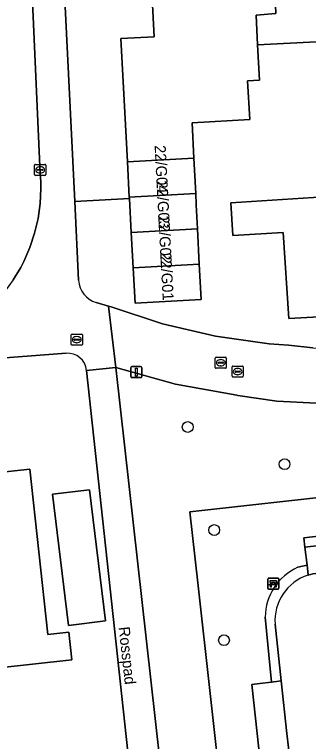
# Model space of a CAD drawing. Extents: x 161248 to 161848, y 384871 to 385383.
# Drawn here: x 161394.3 to 161420.9, y 385265.7 to 385331.7 of the extents above; entities that cross this region are included whole.
import ezdxf

# ---------------------------------------------------------------- set-up
doc = ezdxf.new("R2010")
doc.units = 0
for name, color, linetype in [('IMGEO_Bank', 7, 'Continuous'), ('IMGEO_Boom', 7, 'Continuous'), ('IMGEO_Brandkraan', 7, 'Continuous'), ('IMGEO_Erf', 7, 'Continuous'), ('IMGEO_Groenvoorziening', 7, 'Continuous'), ('IMGEO_Hek', 7, 'Continuous'), ('IMGEO_Kolk', 7, 'Continuous'), ('IMGEO_Lichtmast', 7, 'Continuous'), ('IMGEO_Openbare_ruimte_label', 7, 'Continuous'), ('IMGEO_Pand', 7, 'Continuous'), ('IMGEO_Pand_nummerreeks', 7, 'Continuous'), ('IMGEO_Rijbaan_lokaal_open', 7, 'Continuous'), ('IMGEO_Rioolput', 7, 'Continuous'), ('IMGEO_Voetpad_gesloten', 7, 'Continuous'), ('IMGEO_Voetpad_open', 7, 'Continuous')]:
    doc.layers.add(name, color=color, linetype=linetype)

msp = doc.modelspace()

# ---------------------------------------------------------------- linework, layer by layer
at = {"layer": 'IMGEO_Bank'}
for p, q in [((161417.227, 385279.617), (161417.227, 385280.458)), ((161417.227, 385280.458), (161417.227, 385279.617)), ((161417.302, 385280.542), (161418.143, 385280.542)), ((161418.143, 385280.542), (161417.302, 385280.542)), ((161418.227, 385280.467), (161418.227, 385279.626)), ((161418.227, 385279.626), (161418.227, 385280.467)), ((161417.924, 385279.94), (161417.531, 385279.94)), ((161417.536, 385280.048), (161417.536, 385280.154)), ((161417.58, 385280.154), (161417.58, 385280.048)), ((161417.868, 385280.16), (161417.586, 385280.16)), ((161417.586, 385280.042), (161417.868, 385280.042)), ((161417.874, 385280.048), (161417.874, 385280.154)), ((161417.918, 385280.154), (161417.918, 385280.048)), ((161418.152, 385279.542), (161417.311, 385279.542)), ((161417.311, 385279.542), (161418.152, 385279.542))]:
    msp.add_line(p, q, dxfattribs=at)
for points in [[(161417.474, 385279.94), (161417.332, 385279.94), (161417.444, 385280.042), (161417.53, 385280.042)], [(161417.53, 385280.16), (161417.444, 385280.16), (161417.444, 385280.321), (161418.007, 385280.321), (161418.007, 385280.16), (161417.924, 385280.16)], [(161417.524, 385279.933), (161417.524, 385279.726), (161417.481, 385279.726), (161417.481, 385279.933)], [(161417.924, 385280.042), (161418.007, 385280.042), (161418.119, 385279.94), (161417.98, 385279.94)], [(161417.974, 385279.933), (161417.974, 385279.726), (161417.93, 385279.726), (161417.93, 385279.933)]]:
    msp.add_lwpolyline(points, dxfattribs=at)
for centre, radius, start, end in [((161417.305, 385280.464), 0.0779, 92.4484, 184.28452), ((161417.305, 385280.464), 0.0779, 92.4484, 184.28452), ((161418.149, 385280.464), 0.0779, 2.4484, 94.28452), ((161418.149, 385280.464), 0.0779, 2.4484, 94.28452), ((161417.474, 385279.933), 0.00671, 2.89567, 87.10433), ((161417.531, 385279.933), 0.00671, 92.89567, 177.10433), ((161417.529, 385280.153), 0.00671, 2.89567, 87.10433), ((161417.529, 385280.049), 0.00671, 272.89567, 357.10433), ((161417.586, 385280.153), 0.00671, 92.89567, 177.10433), ((161417.586, 385280.049), 0.00671, 182.89567, 267.10433), ((161417.868, 385280.153), 0.00671, 2.89567, 87.10433), ((161417.868, 385280.049), 0.00671, 272.89567, 357.10433), ((161417.925, 385280.153), 0.00671, 92.89567, 177.10433), ((161417.925, 385280.049), 0.00671, 182.89567, 267.10433), ((161417.923, 385279.933), 0.00671, 2.89567, 87.10433), ((161417.98, 385279.933), 0.00671, 92.89567, 177.10433), ((161417.305, 385279.62), 0.0779, 182.4484, 274.28452), ((161417.305, 385279.62), 0.0779, 182.4484, 274.28452), ((161418.149, 385279.62), 0.0779, 272.4484, 4.28452), ((161418.149, 385279.62), 0.0779, 272.4484, 4.28452)]:
    msp.add_arc(centre, radius, start, end, dxfattribs=at)
at = {"layer": 'IMGEO_Boom'}
for centre in [(161409.973, 385294.249), (161418.745, 385290.874), (161412.374, 385284.907), (161413.26, 385274.915)]:
    msp.add_circle(centre, 0.489, dxfattribs=at)
at = {"layer": 'IMGEO_Brandkraan'}
for p, q in [((161399.432, 385301.745), (161399.432, 385302.597)), ((161399.507, 385302.671), (161400.359, 385302.671)), ((161399.691, 385302.165), (161399.691, 385302.177)), ((161399.734, 385302.214), (161400.132, 385302.214)), ((161399.92, 385302.451), (161399.945, 385302.451)), ((161400.175, 385302.177), (161400.175, 385302.165)), ((161400.433, 385302.597), (161400.433, 385301.745)), ((161400.359, 385301.671), (161399.507, 385301.671)), ((161400.129, 385302.128), (161399.731, 385302.128)), ((161399.943, 385301.891), (161399.918, 385301.891))]:
    msp.add_line(p, q, dxfattribs=at)
for points in [[(161399.432, 385301.745), (161399.432, 385302.597)], [(161399.507, 385302.671), (161400.359, 385302.671)], [(161400.433, 385302.597), (161400.433, 385301.745)], [(161400.359, 385301.671), (161399.507, 385301.671)]]:
    msp.add_lwpolyline(points, dxfattribs=at)
for centre, radius, start, end in [((161399.509, 385302.595), 0.0765, 91.55205, 178.44795), ((161399.509, 385302.595), 0.0765, 91.55205, 178.44795), ((161399.731, 385302.174), 0.0403, 85.87752, 175.75265), ((161399.728, 385302.164), 0.0366, 178.93798, 274.71019), ((161400.132, 385302.171), 0.043, 264.86636, 352.45326), ((161400.136, 385302.176), 0.0386, 1.73085, 96.63898), ((161400.357, 385302.595), 0.0765, 1.55205, 88.44795), ((161400.357, 385302.595), 0.0765, 1.55205, 88.44795), ((161399.509, 385301.747), 0.0765, 181.55205, 268.44795), ((161399.509, 385301.747), 0.0765, 181.55205, 268.44795), ((161400.357, 385301.747), 0.0765, 271.55205, 358.44795), ((161400.357, 385301.747), 0.0765, 271.55205, 358.44795)]:
    msp.add_arc(centre, radius, start, end, dxfattribs=at)
for centre, major_axis, ratio, start_param, end_param in [((161399.919, 385302.171), (-0.387, 0.002), 0.722429, 4.712389, 7.853982), ((161399.944, 385302.171), (-0.39, 0.002), 0.717154, 1.570796, 4.712389)]:
    msp.add_ellipse(centre, major_axis=major_axis, ratio=ratio, start_param=start_param, end_param=end_param, dxfattribs=at)
at = {"layer": 'IMGEO_Erf'}
for points in [[(161398.601, 385337.878), (161399.745, 385314.686), (161404.692, 385314.964), (161404.684, 385315.106), (161404.511, 385318.31), (161403.906, 385329.475), (161406.945, 385329.635), (161406.547, 385337.179)], [(161423.98, 385329.306), (161416.302, 385328.911), (161416.466, 385325.699), (161415.383, 385325.643), (161415.587, 385322.128), (161410.366, 385321.824), (161410.531, 385318.619), (161410.695, 385315.414), (161410.748, 385314.385), (161410.86, 385312.21), (161411.024, 385309.005), (161411.189, 385305.8), (161405.205, 385305.492), (161405.031, 385308.697), (161404.858, 385311.901), (161404.692, 385314.964), (161399.745, 385314.686), (161400.097, 385307.562)], [(161401.692, 385305.534), (161402.809, 385305.204), (161403.042, 385305.135), (161407.703, 385303.597), (161412.483, 385302.481), (161417.343, 385301.797), (161419.104, 385301.658), (161421.316, 385301.428), (161423.54, 385301.396), (161425.328, 385301.515), (161433.495, 385302.03), (161432.821, 385315.408)], [(161398.96, 385300.934), (161391.455, 385300.374)], [(161391.744, 385183.5), (161396.212, 385183.986), (161401.98, 385184.625), (161402.139, 385184.643), (161406.592, 385185.134), (161412.682, 385185.849), (161413.106, 385185.96), (161411.781, 385198.48), (161406.165, 385250), (161400.82, 385299.379)], [(161379.033, 385288.611), (161395.673, 385290.437), (161397.318, 385275.442), (161399.197, 385275.648), (161399.473, 385273.133), (161382.449, 385271.265)]]:
    msp.add_lwpolyline(points, dxfattribs=at)
for points in [[(161426.057, 385315.361), (161426.125, 385314.29), (161430.906, 385314.594), (161431.245, 385309.259), (161431.911, 385309.3), (161432.236, 385304.186), (161421.893, 385303.639), (161421.861, 385304.249), (161419.12, 385304.103), (161418.623, 385311.901), (161414.063, 385311.61), (161413.873, 385314.584)], [(161399.175, 385276.249), (161397.723, 385288.146), (161401.081, 385288.556), (161402.534, 385276.659)]]:
    msp.add_lwpolyline(points, close=True, dxfattribs=at)
for centre, radius, start, end in [((161402.323, 385307.672), 2.229, 182.81721, 253.55213), ((161399.091, 385299.2), 1.739, 5.89689, 94.31041)]:
    msp.add_arc(centre, radius, start, end, dxfattribs=at)
at = {"layer": 'IMGEO_Groenvoorziening'}
for points in [[(161414.256, 385250), (161410.885, 385280.109), (161410.162, 385286.563), (161475.044, 385293.779), (161521.676, 385299.004), (161534.85, 385300.481), (161543.938, 385301.499), (161569.562, 385304.383), (161586.988, 385306.345), (161622.8, 385310.376), (161633.809, 385311.615), (161634.458, 385305.787), (161634.818, 385302.549), (161643.668, 385222.865)], [(161543.364, 385306.723), (161500, 385302.086), (161474.798, 385299.391), (161474.909, 385297.26), (161471.889, 385297.103), (161471.879, 385297.287), (161464.205, 385296.931), (161464.206, 385296.907), (161462.414, 385296.814), (161462.412, 385296.848), (161450.838, 385296.312), (161450.732, 385298.359), (161445.594, 385298.092), (161445.597, 385297.541), (161424.736, 385296.492), (161421.626, 385296.405), (161418.051, 385296.604), (161414.509, 385297.121), (161414.415, 385297.134), (161408.88, 385298.145), (161403.458, 385299.646), (161409.014, 385250)], [(161419.938, 385281.527), (161420.776, 385281.731), (161420.588, 385283.368), (161420.493, 385284.196), (161444.677, 385286.979), (161444.772, 385286.151), (161445.027, 385283.936), (161445.061, 385283.659), (161449.189, 385284.134), (161448.902, 385286.626), (161448.807, 385287.454), (161521.926, 385295.866), (161521.676, 385299.004), (161475.044, 385293.779), (161410.162, 385286.563), (161410.885, 385280.109), (161414.256, 385250)], [(161420.878, 385280.815), (161420.843, 385281.153), (161420.776, 385281.731), (161419.938, 385281.527)], [(161416.555, 385263.685), (161415.768, 385270.902), (161416.49, 385270.991), (161417.55, 385271.121), (161416.996, 385277.006)], [(161416.996, 385277.006), (161417.55, 385271.121), (161418.237, 385271.205), (161418.44, 385271.231), (161417.881, 385276.364)]]:
    msp.add_lwpolyline(points, dxfattribs=at)
for points in [[(161444.772, 385286.151), (161444.677, 385286.979), (161420.493, 385284.196), (161420.588, 385283.368)], [(161445.061, 385283.659), (161445.027, 385283.936), (161444.772, 385286.151), (161420.588, 385283.368), (161420.776, 385281.731), (161420.843, 385281.153), (161420.878, 385280.815), (161421.089, 385280.877), (161421.302, 385280.928)], [(161418.44, 385271.231), (161418.237, 385271.205), (161417.55, 385271.121), (161416.49, 385270.991), (161415.768, 385270.902), (161416.555, 385263.685), (161417.863, 385263.793), (161419.035, 385263.89), (161419.237, 385263.908), (161418.959, 385266.457)]]:
    msp.add_lwpolyline(points, close=True, dxfattribs=at)
for centre, radius, start, end in [((161421.995, 385276.97), 4.999, 114.29995, 179.59264), ((161421.995, 385276.97), 4.999, 114.29995, 179.59264), ((161422.208, 385276.685), 4.339, 107.8532, 184.23952)]:
    msp.add_arc(centre, radius, start, end, dxfattribs=at)
at = {"layer": 'IMGEO_Hek'}
for points in [[(161410.162, 385286.563), (161475.044, 385293.779)], [(161410.885, 385280.109), (161410.162, 385286.563)], [(161418.32, 385212.789), (161414.256, 385250), (161410.885, 385280.109)]]:
    msp.add_lwpolyline(points, dxfattribs=at)
at = {"layer": 'IMGEO_Kolk'}
for p, q in [((161396.116, 385317.142), (161396.116, 385317.994)), ((161396.191, 385318.068), (161397.043, 385318.068)), ((161397.117, 385317.994), (161397.117, 385317.142)), ((161396.375, 385317.562), (161396.375, 385317.574)), ((161396.813, 385317.525), (161396.415, 385317.525)), ((161396.418, 385317.611), (161396.816, 385317.611)), ((161396.604, 385317.848), (161396.629, 385317.848)), ((161396.859, 385317.574), (161396.859, 385317.562)), ((161397.043, 385317.068), (161396.191, 385317.068)), ((161396.627, 385317.288), (161396.602, 385317.288)), ((161412.466, 385299.651), (161412.466, 385300.503)), ((161412.541, 385300.577), (161413.393, 385300.577)), ((161412.954, 385300.357), (161412.979, 385300.357)), ((161413.467, 385300.503), (161413.467, 385299.651)), ((161413.393, 385299.577), (161412.541, 385299.577)), ((161412.725, 385300.071), (161412.725, 385300.083)), ((161413.163, 385300.034), (161412.765, 385300.034)), ((161412.768, 385300.12), (161413.166, 385300.12)), ((161412.977, 385299.797), (161412.952, 385299.797)), ((161413.209, 385300.083), (161413.209, 385300.071))]:
    msp.add_line(p, q, dxfattribs=at)
for points in [[(161396.116, 385317.142), (161396.116, 385317.994)], [(161396.191, 385318.068), (161397.043, 385318.068)], [(161397.117, 385317.994), (161397.117, 385317.142)], [(161397.043, 385317.068), (161396.191, 385317.068)], [(161412.466, 385299.651), (161412.466, 385300.503)], [(161412.541, 385300.577), (161413.393, 385300.577)], [(161413.467, 385300.503), (161413.467, 385299.651)], [(161413.393, 385299.577), (161412.541, 385299.577)]]:
    msp.add_lwpolyline(points, dxfattribs=at)
for centre, radius, start, end in [((161396.193, 385317.992), 0.0765, 91.55205, 178.44795), ((161396.193, 385317.992), 0.0765, 91.55205, 178.44795), ((161397.041, 385317.992), 0.0765, 1.55205, 88.44795), ((161397.041, 385317.992), 0.0765, 1.55205, 88.44795), ((161396.415, 385317.571), 0.0403, 85.87752, 175.75265), ((161396.412, 385317.561), 0.0366, 178.93798, 274.71019), ((161396.816, 385317.568), 0.043, 264.86636, 352.45326), ((161396.82, 385317.573), 0.0386, 1.73085, 96.63898), ((161396.193, 385317.144), 0.0765, 181.55205, 268.44795), ((161396.193, 385317.144), 0.0765, 181.55205, 268.44795), ((161397.041, 385317.144), 0.0765, 271.55205, 358.44795), ((161397.041, 385317.144), 0.0765, 271.55205, 358.44795), ((161412.543, 385300.501), 0.0765, 91.55205, 178.44795), ((161412.543, 385300.501), 0.0765, 91.55205, 178.44795), ((161413.391, 385300.501), 0.0765, 1.55205, 88.44795), ((161413.391, 385300.501), 0.0765, 1.55205, 88.44795), ((161412.543, 385299.653), 0.0765, 181.55205, 268.44795), ((161412.543, 385299.653), 0.0765, 181.55205, 268.44795), ((161412.765, 385300.08), 0.0403, 85.87752, 175.75265), ((161412.762, 385300.07), 0.0366, 178.93798, 274.71019), ((161413.166, 385300.077), 0.043, 264.86636, 352.45326), ((161413.17, 385300.082), 0.0386, 1.73085, 96.63898), ((161413.391, 385299.653), 0.0765, 271.55205, 358.44795), ((161413.391, 385299.653), 0.0765, 271.55205, 358.44795)]:
    msp.add_arc(centre, radius, start, end, dxfattribs=at)
for centre, major_axis, ratio, start_param, end_param in [((161396.603, 385317.568), (-0.387, 0.002), 0.722429, 4.712389, 7.853982), ((161396.628, 385317.568), (-0.39, 0.002), 0.717154, 1.570796, 4.712389), ((161412.953, 385300.077), (-0.387, 0.002), 0.722429, 4.712389, 7.853982), ((161412.978, 385300.077), (-0.39, 0.002), 0.717154, 1.570796, 4.712389)]:
    msp.add_ellipse(centre, major_axis=major_axis, ratio=ratio, start_param=start_param, end_param=end_param, dxfattribs=at)
at = {"layer": 'IMGEO_Lichtmast'}
for p, q in [((161404.819, 385298.824), (161404.819, 385299.624)), ((161404.819, 385299.624), (161404.819, 385298.824)), ((161404.919, 385299.724), (161405.709, 385299.724)), ((161405.709, 385299.724), (161404.919, 385299.724)), ((161405.809, 385299.624), (161405.809, 385298.824)), ((161405.809, 385298.824), (161405.809, 385299.624)), ((161405.709, 385298.724), (161404.919, 385298.724)), ((161404.919, 385298.724), (161405.709, 385298.724))]:
    msp.add_line(p, q, dxfattribs=at)
msp.add_lwpolyline([(161405.239, 385299.599), (161405.389, 385299.599), (161405.389, 385298.849), (161405.239, 385298.849), (161405.239, 385299.599)], dxfattribs=at)
for centre, start, end in [((161404.919, 385299.624), 90, 180), ((161404.919, 385299.624), 90, 180), ((161405.709, 385299.624), 0, 90), ((161405.709, 385299.624), 360, 90), ((161404.919, 385298.824), 180, 270), ((161404.919, 385298.824), 180, 270), ((161405.709, 385298.824), 270, 0), ((161405.709, 385298.824), 270, 0)]:
    msp.add_arc(centre, 0.1, start, end, dxfattribs=at)
at = {"layer": 'IMGEO_Pand'}
for points in [[(161427.998, 385338.318), (161419.808, 385337.885), (161419.889, 385336.345), (161417.772, 385336.233), (161417.951, 385331.733), (161416.162, 385331.603), (161416.302, 385328.911), (161423.98, 385329.306), (161424.53, 385318.636), (161425.276, 385318.674), (161428.76, 385318.853), (161429.025, 385318.867)], [(161413.405, 385336.002), (161413.324, 385337.537), (161406.547, 385337.179), (161406.945, 385329.635), (161403.906, 385329.475), (161404.511, 385318.31), (161410.531, 385318.619), (161410.366, 385321.824), (161415.587, 385322.128), (161415.383, 385325.643), (161416.466, 385325.699), (161416.302, 385328.911), (161416.162, 385331.603), (161417.951, 385331.733), (161417.772, 385336.233)], [(161404.684, 385315.106), (161410.695, 385315.414), (161410.531, 385318.619), (161404.511, 385318.31)], [(161404.692, 385314.964), (161404.858, 385311.901), (161410.86, 385312.21), (161410.748, 385314.385), (161410.695, 385315.414), (161404.684, 385315.106)], [(161414.063, 385311.61), (161418.623, 385311.901), (161419.12, 385304.103), (161421.861, 385304.249), (161421.893, 385303.639), (161432.236, 385304.186), (161431.911, 385309.3), (161431.245, 385309.259), (161430.906, 385314.594), (161426.125, 385314.29), (161426.057, 385315.361), (161413.873, 385314.584)], [(161405.031, 385308.697), (161411.024, 385309.005), (161410.86, 385312.21), (161404.858, 385311.901)], [(161405.205, 385305.492), (161411.189, 385305.8), (161411.024, 385309.005), (161405.031, 385308.697)], [(161399.175, 385276.249), (161402.534, 385276.659), (161401.081, 385288.556), (161397.723, 385288.146)]]:
    msp.add_lwpolyline(points, close=True, dxfattribs=at)
msp.add_lwpolyline([(161382.449, 385271.265), (161399.473, 385273.133), (161399.197, 385275.648), (161397.318, 385275.442), (161395.673, 385290.437), (161379.033, 385288.611)], dxfattribs=at)
at = {"layer": 'IMGEO_Rijbaan_lokaal_open'}
for points in [[(161394.178, 385307.586), (161394.868, 385308.726), (161395.144, 385309.256), (161395.685, 385310.515), (161396.112, 385311.817), (161396.42, 385313.152), (161396.609, 385314.509), (161396.675, 385315.878), (161396.664, 385316.508), (161396.614, 385317.218), (161395.736, 385336.901)], [(161421.316, 385301.428), (161419.104, 385301.658), (161417.343, 385301.797), (161412.483, 385302.481), (161407.703, 385303.597), (161403.042, 385305.135), (161402.809, 385305.204), (161403.458, 385299.646), (161408.88, 385298.145), (161414.415, 385297.134), (161414.509, 385297.121), (161418.051, 385296.604), (161421.626, 385296.405)]]:
    msp.add_lwpolyline(points, dxfattribs=at)
at = {"layer": 'IMGEO_Rioolput'}
for p, q in [((161413.997, 385298.848), (161413.997, 385299.7)), ((161414.072, 385299.774), (161414.924, 385299.774)), ((161414.485, 385299.554), (161414.51, 385299.554)), ((161414.998, 385299.7), (161414.998, 385298.848)), ((161414.256, 385299.268), (161414.256, 385299.28)), ((161414.694, 385299.231), (161414.296, 385299.231)), ((161414.299, 385299.317), (161414.697, 385299.317)), ((161414.508, 385298.994), (161414.483, 385298.994)), ((161414.74, 385299.28), (161414.74, 385299.268)), ((161414.924, 385298.774), (161414.072, 385298.774))]:
    msp.add_line(p, q, dxfattribs=at)
for points in [[(161413.997, 385298.848), (161413.997, 385299.7)], [(161414.072, 385299.774), (161414.924, 385299.774)], [(161414.998, 385299.7), (161414.998, 385298.848)], [(161414.924, 385298.774), (161414.072, 385298.774)]]:
    msp.add_lwpolyline(points, dxfattribs=at)
for centre, radius, start, end in [((161414.074, 385299.698), 0.0765, 91.55205, 178.44795), ((161414.074, 385299.698), 0.0765, 91.55205, 178.44795), ((161414.922, 385299.698), 0.0765, 1.55205, 88.44795), ((161414.922, 385299.698), 0.0765, 1.55205, 88.44795), ((161414.074, 385298.85), 0.0765, 181.55205, 268.44795), ((161414.074, 385298.85), 0.0765, 181.55205, 268.44795), ((161414.296, 385299.277), 0.0403, 85.87752, 175.75265), ((161414.293, 385299.267), 0.0366, 178.93798, 274.71019), ((161414.697, 385299.274), 0.043, 264.86636, 352.45326), ((161414.701, 385299.279), 0.0386, 1.73085, 96.63898), ((161414.922, 385298.85), 0.0765, 271.55205, 358.44795), ((161414.922, 385298.85), 0.0765, 271.55205, 358.44795)]:
    msp.add_arc(centre, radius, start, end, dxfattribs=at)
for centre, major_axis, ratio, start_param, end_param in [((161414.484, 385299.274), (-0.387, 0.002), 0.722429, 4.712389, 7.853982), ((161414.509, 385299.274), (-0.39, 0.002), 0.717154, 1.570796, 4.712389)]:
    msp.add_ellipse(centre, major_axis=major_axis, ratio=ratio, start_param=start_param, end_param=end_param, dxfattribs=at)
at = {"layer": 'IMGEO_Voetpad_gesloten'}
for points in [[(161566.889, 385297.751), (161535.413, 385294.069), (161523.879, 385292.72), (161522.31, 385292.54), (161449.189, 385284.134), (161445.061, 385283.659), (161421.302, 385280.928), (161421.089, 385280.877), (161420.878, 385280.815)], [(161417.881, 385276.364), (161418.44, 385271.231), (161418.959, 385266.457), (161419.237, 385263.908), (161420.964, 385248.092), (161421.223, 385245.715), (161422.767, 385231.573), (161425.115, 385210.061), (161426.369, 385198.57), (161428.216, 385181.647), (161434.587, 385123.289), (161437.317, 385098.274), (161437.566, 385096.339), (161437.632, 385095.831), (161438.183, 385093.977), (161438.834, 385093.495), (161439.577, 385093.264), (161440.609, 385093.05), (161441.669, 385092.83), (161442.358, 385092.869), (161464.945, 385095.485), (161477.693, 385096.962)]]:
    msp.add_lwpolyline(points, dxfattribs=at)
msp.add_arc((161422.208, 385276.685), 4.339, 107.8532, 184.23952, dxfattribs=at)
at = {"layer": 'IMGEO_Voetpad_open'}
for points in [[(161400.097, 385307.562), (161399.745, 385314.686), (161398.601, 385337.878), (161395.736, 385336.901), (161396.614, 385317.218), (161396.664, 385316.508), (161396.675, 385315.878), (161396.609, 385314.509), (161396.42, 385313.152), (161396.112, 385311.817), (161395.685, 385310.515), (161395.144, 385309.256), (161394.868, 385308.726), (161394.178, 385307.586), (161393.388, 385306.512), (161392.505, 385305.512), (161391.537, 385304.596)], [(161402.809, 385305.204), (161401.692, 385305.534)], [(161400.82, 385299.379), (161403.458, 385299.646), (161402.809, 385305.204)], [(161331.859, 385277.42), (161354.019, 385285.915), (161357.516, 385287.256), (161373.799, 385293.574), (161391.455, 385300.374), (161398.96, 385300.934)]]:
    msp.add_lwpolyline(points, dxfattribs=at)
msp.add_lwpolyline([(161403.458, 385299.646), (161400.82, 385299.379), (161406.165, 385250), (161411.781, 385198.48), (161413.106, 385185.96), (161415.386, 385165.844), (161418.12, 385166.146), (161414.353, 385200.201), (161414.19, 385201.677), (161413.061, 385212.221), (161409.014, 385250)], close=True, dxfattribs=at)
for centre, radius, start, end in [((161402.323, 385307.672), 2.229, 182.81721, 253.55213), ((161399.091, 385299.2), 1.739, 5.89689, 94.31041)]:
    msp.add_arc(centre, radius, start, end, dxfattribs=at)

# ---------------------------------------------------------------- texts
at = {"layer": 'IMGEO_Openbare_ruimte_label'}
msp.add_text('Rosspad', height=1, rotation=276.20097, dxfattribs=at).set_placement((161403.718, 385276.096))
at = {"layer": 'IMGEO_Pand_nummerreeks'}
for s, rotation, p in [('22/G04', 272.94015, (161406.976, 385319.784)), ('22/G03', 272.94015, (161407.141, 385316.58)), ('22/G02', 273.1003, (161407.301, 385313.388)), ('22/G01', 273.1003, (161407.481, 385310.067))]:
    msp.add_text(s, height=1, rotation=rotation, dxfattribs=at).set_placement(p)

doc.saveas('drawing.dxf')
